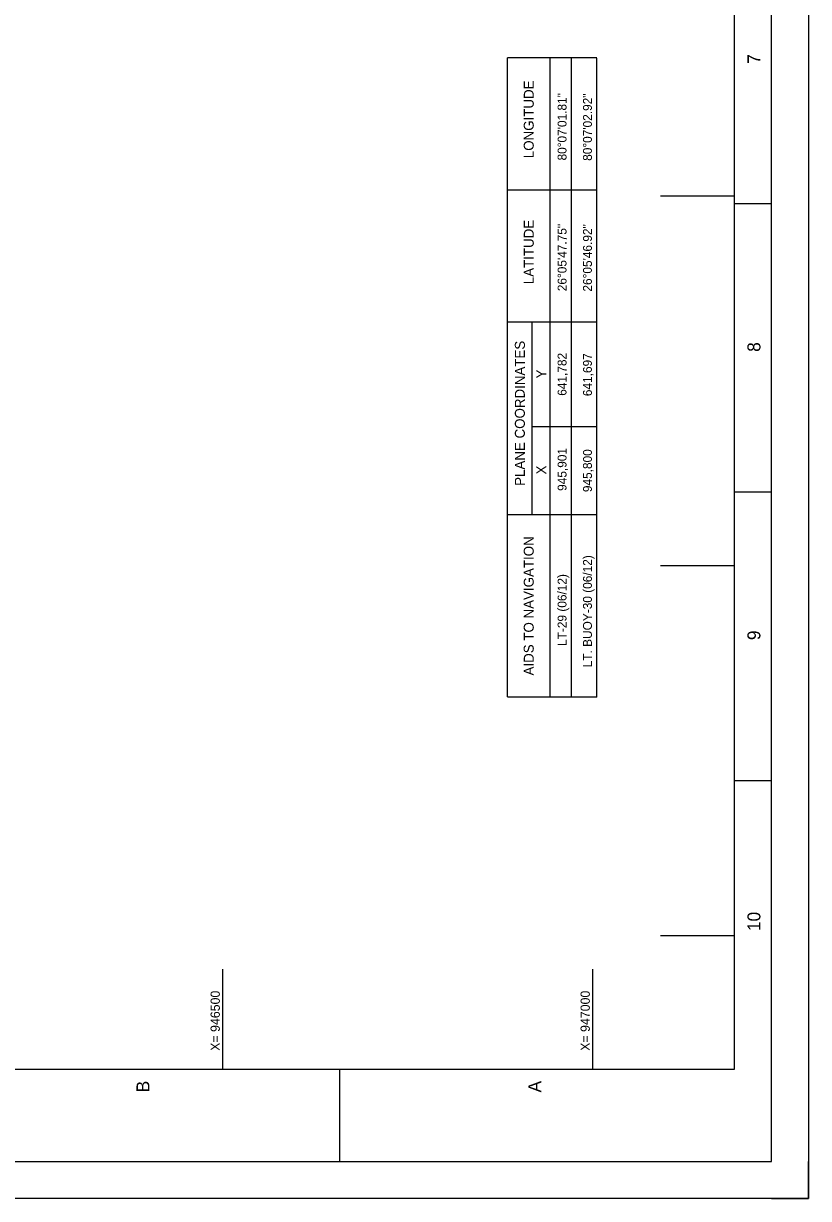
# Model space of a CAD drawing. Extents: x 943892 to 947291, y 640645 to 645045.
# Drawn here: x 946231 to 947291, y 640645 to 642234 of the extents above; entities that cross this region are included whole.
import ezdxf

# ---------------------------------------------------------------- set-up
doc = ezdxf.new("R2010")
doc.units = 0
for name, color, linetype in [('G-ANNO-NPLT', 7, 'Continuous'), ('G-ANNO-TTLB', 7, 'Continuous'), ('V-ANNO-SCHD', 7, 'Continuous'), ('V-ANNO-SYMB', 7, 'Continuous'), ('V-TOPO-COOR-STAT', 7, 'Continuous')]:
    doc.layers.add(name, color=color, linetype=linetype)

msp = doc.modelspace()

# ---------------------------------------------------------------- linework, layer by layer
at = {"layer": 'G-ANNO-NPLT'}
msp.add_lwpolyline([(943891.5, 640644.6), (943891.5, 645044.6), (947291.5, 645044.6), (947291.5, 640644.6)], close=True, dxfattribs=at)
msp.add_lwpolyline([(947241.5, 640644.6), (947291.5, 640644.6), (947291.5, 640694.6)], dxfattribs=at)
at = {"layer": 'G-ANNO-TTLB'}
for p, q in [((947241.5, 641989.6), (947191.5, 641989.6)), ((947241.5, 641599.6), (947191.5, 641599.6)), ((947241.5, 641209.6), (947191.5, 641209.6)), ((946658.2, 640694.6), (946658.2, 640819.6))]:
    msp.add_line(p, q, dxfattribs=at)
for points in [[(947241.5, 640694.6), (947241.5, 644994.6), (943941.5, 644994.6), (943941.5, 640694.6)], [(943991.5, 644944.6), (943991.5, 640819.6), (947191.5, 640819.6), (947191.5, 644944.6)]]:
    msp.add_lwpolyline(points, close=True, dxfattribs=at)
at = {"layer": 'V-ANNO-SCHD'}
for p, q in [((946884.6, 641323), (946884.6, 642187)), ((947005.5, 642187), (946884.6, 642187)), ((946942.4, 641323), (946942.4, 642187)), ((946971.2, 641323), (946971.2, 642187)), ((947005.5, 641322.5), (947005.5, 642186.5)), ((946884.6, 642008.7), (947005.5, 642008.7)), ((946884.6, 641830.3), (947005.5, 641830.3)), ((946918.3, 641569.6), (946918.3, 641830.3)), ((946918.3, 641688.5), (947005.5, 641688.5)), ((946884.6, 641569.6), (947005.5, 641569.6)), ((946884.6, 641323), (947005.5, 641323))]:
    msp.add_line(p, q, dxfattribs=at)
at = {"layer": 'V-TOPO-COOR-STAT'}
for p, q in [((947191.5, 642000), (947091.5, 642000)), ((947191.5, 641500), (947091.5, 641500)), ((947191.5, 641000), (947091.5, 641000)), ((946500, 640819.6), (946500, 640954.6)), ((947000, 640819.6), (947000, 640954.6))]:
    msp.add_line(p, q, dxfattribs=at)

# ---------------------------------------------------------------- texts
at = {"layer": 'G-ANNO-TTLB'}
for s, p in [('7', (947226.5, 642179)), ('8', (947226.5, 641789.5)), ('9', (947226.5, 641399.7)), ('10', (947226.5, 641006.2)), ('A', (946930.3, 640788)), ('B', (946400.8, 640788.2))]:
    msp.add_text(s, height=17.5, rotation=90, dxfattribs=at).set_placement(p)
at = {"layer": 'V-ANNO-SCHD'}
for s, height, p in [('LONGITUDE', 13.47, (946920.2, 642051.4)), ('LATITUDE', 13.47, (946920.2, 641881)), ('PLANE COORDINATES', 13.471, (946908.2, 641608.3)), ('Y', 13.5, (946937.1, 641753.5)), ('X', 13.5, (946937.1, 641623.7)), ('AIDS TO NAVIGATION', 13.471, (946920.2, 641351.9))]:
    msp.add_text(s, height=height, rotation=90.0001, dxfattribs=at).set_placement(p)
at = {"layer": 'V-ANNO-SYMB'}
for s, p in [('80%%D07\'01.81"', (946964.5, 642048.3)), ('80%%D07\'02.92"', (946998.8, 642047.8)), ('26%%D05\'47.75"', (946964.5, 641871.5)), ('26%%D05\'46.92"', (946998.8, 641871)), ('641,782', (946964.5, 641730.1)), ('641,697', (946998.8, 641729.6)), ('945,901', (946964.5, 641601.5)), ('945,800', (946998.8, 641599.8)), ('LT. BUOY-30 (06/12)', (946998.8, 641362.9)), ('LT-29 (06/12)', (946964.5, 641391.8))]:
    msp.add_text(s, height=12, rotation=90, dxfattribs=at).set_placement(p)
at = {"layer": 'V-TOPO-COOR-STAT'}
for s, p in [('X= 946500', (946496, 640844.3)), ('X= 947000', (946996, 640844.3))]:
    msp.add_text(s, height=12.5, rotation=90, dxfattribs=at).set_placement(p)

doc.saveas('drawing.dxf')
